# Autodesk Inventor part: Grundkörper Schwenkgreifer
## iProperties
Shininess: 20.0
Length Units: 11269
Angle Units: 11279
Time Units: 11290
Mass Units: 11283
Length Display Precision: 3
Angle Display Precision: 2
Company: Rhodius GmbH
Part Number: Grundkörper Schwenkgreifer
Material: Standard
Document SubType Name: Modeling
Cost Center: Abtlg. Technik
Designer: KOPP
Created: 2003-05
Density: 0.0
Volumn: 0.0
Area: 0.0
PropertySet Name: Model Information
Control State: 0
Master: False
Checked Out: False
Author: KOPP
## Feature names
1. Extrusion1
2. Bohrung1 [Hole]
3. Bohrung2 [Hole]
